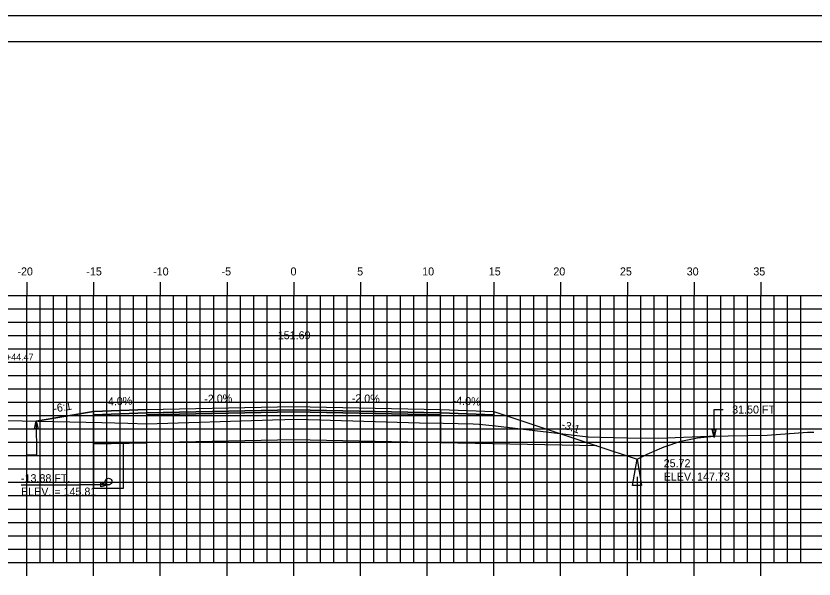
# Model space of a CAD drawing. Extents: x 1147412 to 1147582, y 608981 to 609091.
# Drawn here: x 1147473.9 to 1147533.7, y 609049.1 to 609091.3 of the extents above; entities that cross this region are included whole.
import ezdxf

# ---------------------------------------------------------------- set-up
doc = ezdxf.new("R2010")
doc.units = 0
for name, color, linetype in [('ANNOTATION', 7, 'Continuous'), ('BORDER', 7, 'Continuous'), ('D_Drainage_Ditch_Line', 7, 'Continuous'), ('D_Drainage_Underdrain', 7, 'Continuous'), ('D_Drainage_Underdrain_06in', 7, 'Continuous'), ('D_Roadway_Centerline', 7, 'Continuous'), ('D_Roadway_Centerline_Text', 7, 'Continuous'), ('D_Roadway_Edge_Shoulder', 7, 'Continuous'), ('D_Roadway_Edge_TW', 7, 'Continuous'), ('D_Roadway_Pavement', 7, 'Continuous'), ('D_Roadway_SlopeLines', 7, 'Continuous'), ('D_Roadway_SubGrade', 7, 'Continuous'), ('D_Text_Monospaced', 7, 'Continuous'), ('D_Text_Standard', 7, 'Continuous'), ('H_V ANNOTATION', 7, 'Continuous'), ('MAJOR', 7, 'Continuous'), ('MINOR', 7, 'Continuous'), ('PLOT BOUNDARY', 7, 'Continuous'), ('S_Roadway_Centerline', 7, 'Continuous')]:
    doc.layers.add(name, color=color, linetype=linetype)

msp = doc.modelspace()

# ---------------------------------------------------------------- linework, layer by layer
msp.add_lwpolyline([(1147475.408, 609060.927), (1147479.696, 609061.642), (1147479.697, 609061.642), (1147483.697, 609061.802), (1147494.697, 609062.022), (1147505.697, 609061.802), (1147509.697, 609061.642), (1147517.421, 609059.067), (1147520.421, 609058.067), (1147521.194, 609058.454), (1147522.444, 609059.006), (1147523.694, 609059.415), (1147524.944, 609059.679), (1147526.194, 609059.799)])
at = {"layer": 'BORDER'}
msp.add_lwpolyline([(1147419.698, 608984.335), (1147579.698, 608984.335), (1147579.698, 609089.335), (1147419.698, 609089.335)], close=True, dxfattribs=at)
at = {"layer": 'D_Drainage_Ditch_Line'}
msp.add_line((1147520.421, 609056.755), (1147520.421, 609050.511), dxfattribs=at)
msp.add_lwpolyline([(1147520.749, 609056.099), (1147520.093, 609056.099), (1147520.421, 609058.067)], close=True, dxfattribs=at)
at = {"layer": 'D_Drainage_Underdrain'}
msp.add_lwpolyline([(1147479.697, 609059.222), (1147479.697, 609055.892), (1147481.947, 609055.892), (1147481.947, 609059.267)], close=True, dxfattribs=at)
at = {"layer": 'D_Drainage_Underdrain_06in'}
msp.add_lwpolyline([(1147480.822, 609056.642), (1147480.9, 609056.629), (1147480.969, 609056.594), (1147481.025, 609056.539), (1147481.06, 609056.469), (1147481.072, 609056.392), (1147481.06, 609056.314), (1147481.025, 609056.245), (1147480.969, 609056.189), (1147480.9, 609056.154), (1147480.822, 609056.142), (1147480.745, 609056.154), (1147480.675, 609056.189), (1147480.62, 609056.245), (1147480.585, 609056.314), (1147480.572, 609056.392), (1147480.585, 609056.469), (1147480.62, 609056.539), (1147480.675, 609056.594), (1147480.745, 609056.629)], close=True, dxfattribs=at)
at = {"layer": 'D_Roadway_Edge_Shoulder'}
for points in [[(1147483.697, 609061.802), (1147479.697, 609061.642), (1147479.697, 609061.392), (1147483.697, 609061.552)], [(1147505.697, 609061.802), (1147509.697, 609061.642), (1147509.697, 609061.392), (1147505.697, 609061.552)]]:
    msp.add_lwpolyline(points, close=True, dxfattribs=at)
at = {"layer": 'D_Roadway_Edge_TW'}
msp.add_lwpolyline([(1147483.697, 609061.552), (1147483.697, 609061.802), (1147494.697, 609062.022), (1147505.697, 609061.802), (1147505.697, 609061.552), (1147494.697, 609061.772)], close=True, dxfattribs=at)
at = {"layer": 'D_Roadway_Pavement'}
msp.add_lwpolyline([(1147483.697, 609061.385), (1147483.697, 609061.552), (1147494.697, 609061.772), (1147505.697, 609061.552), (1147505.697, 609061.385), (1147494.697, 609061.605)], close=True, dxfattribs=at)
at = {"layer": 'D_Roadway_SlopeLines'}
for points in [[(1147479.697, 609061.642), (1147475.408, 609060.927)], [(1147520.421, 609058.067), (1147521.194, 609058.454), (1147522.444, 609059.006), (1147523.694, 609059.415), (1147524.944, 609059.679), (1147526.194, 609059.799)], [(1147517.421, 609059.067), (1147520.421, 609058.067)]]:
    msp.add_lwpolyline(points, dxfattribs=at)
at = {"layer": 'D_Roadway_SubGrade'}
for points in [[(1147483.697, 609061.385), (1147483.697, 609061.552), (1147479.697, 609061.392), (1147479.697, 609061.642), (1147479.696, 609061.642), (1147479.697, 609059.222), (1147483.697, 609059.302)], [(1147483.697, 609059.302), (1147483.697, 609061.385), (1147494.697, 609061.605), (1147505.697, 609061.385), (1147505.697, 609059.302), (1147494.697, 609059.522)], [(1147505.697, 609061.385), (1147505.697, 609061.552), (1147509.697, 609061.392), (1147509.697, 609061.642), (1147509.698, 609061.642), (1147517.421, 609059.067), (1147505.697, 609059.302)]]:
    msp.add_lwpolyline(points, close=True, dxfattribs=at)
at = {"layer": 'D_Text_Standard'}
msp.add_line((1147474.26, 609056.142), (1147478.675, 609056.142), dxfattribs=at)
for points in [[(1147526.194, 609059.704), (1147526.192, 609061.789), (1147526.872, 609061.789)], [(1147475.408, 609060.927), (1147475.413, 609058.361), (1147474.733, 609058.361)], [(1147480.822, 609056.142), (1147479.355, 609056.142), (1147478.675, 609056.142)]]:
    msp.add_lwpolyline(points, dxfattribs=at)
for points in [[(1147475.408, 609060.927), (1147475.554, 609060.345), (1147475.263, 609060.344)], [(1147526.194, 609059.704), (1147526.048, 609060.286), (1147526.339, 609060.286)], [(1147480.822, 609056.142), (1147480.24, 609055.996), (1147480.24, 609056.287)]]:
    msp.add_lwpolyline(points, close=True, dxfattribs=at)
at = {"layer": 'MAJOR'}
for p, q in [((1147474.697, 609071.337), (1147474.697, 609070.335)), ((1147479.697, 609071.337), (1147479.697, 609070.335)), ((1147484.697, 609071.337), (1147484.697, 609070.335)), ((1147489.697, 609071.337), (1147489.697, 609070.335)), ((1147494.697, 609071.337), (1147494.697, 609070.335)), ((1147499.697, 609071.337), (1147499.697, 609070.335)), ((1147504.697, 609071.337), (1147504.697, 609070.335)), ((1147509.697, 609071.337), (1147509.697, 609070.335)), ((1147514.697, 609071.337), (1147514.697, 609070.335)), ((1147519.697, 609071.337), (1147519.697, 609070.335)), ((1147524.697, 609071.337), (1147524.697, 609070.335)), ((1147529.697, 609071.337), (1147529.697, 609070.335)), ((1147424.697, 609070.335), (1147564.697, 609070.335)), ((1147424.697, 609070.335), (1147564.697, 609070.335)), ((1147474.697, 609050.335), (1147474.697, 609070.335)), ((1147479.697, 609050.335), (1147479.697, 609070.335)), ((1147484.697, 609050.335), (1147484.697, 609070.335)), ((1147489.697, 609050.335), (1147489.697, 609070.335)), ((1147494.697, 609050.335), (1147494.697, 609070.335)), ((1147499.697, 609050.335), (1147499.697, 609070.335)), ((1147504.697, 609050.335), (1147504.697, 609070.335)), ((1147509.697, 609050.335), (1147509.697, 609070.335)), ((1147514.697, 609050.335), (1147514.697, 609070.335)), ((1147519.697, 609050.335), (1147519.697, 609070.335)), ((1147524.697, 609050.335), (1147524.697, 609070.335)), ((1147529.697, 609050.335), (1147529.697, 609070.335)), ((1147424.697, 609065.335), (1147564.697, 609065.335)), ((1147424.697, 609060.335), (1147564.697, 609060.335)), ((1147424.697, 609055.335), (1147564.697, 609055.335)), ((1147424.697, 609050.335), (1147564.697, 609050.335)), ((1147424.697, 609050.335), (1147564.697, 609050.335)), ((1147474.697, 609049.333), (1147474.697, 609050.335)), ((1147479.697, 609049.333), (1147479.697, 609050.335)), ((1147484.697, 609049.333), (1147484.697, 609050.335)), ((1147489.697, 609049.333), (1147489.697, 609050.335)), ((1147494.697, 609049.333), (1147494.697, 609050.335)), ((1147499.697, 609049.333), (1147499.697, 609050.335)), ((1147504.697, 609049.333), (1147504.697, 609050.335)), ((1147509.697, 609049.333), (1147509.697, 609050.335)), ((1147514.697, 609049.333), (1147514.697, 609050.335)), ((1147519.697, 609049.333), (1147519.697, 609050.335)), ((1147524.697, 609049.333), (1147524.697, 609050.335)), ((1147529.697, 609049.333), (1147529.697, 609050.335))]:
    msp.add_line(p, q, dxfattribs=at)
at = {"layer": 'MINOR'}
for p, q in [((1147475.697, 609050.335), (1147475.697, 609070.335)), ((1147476.697, 609050.335), (1147476.697, 609070.335)), ((1147477.697, 609050.335), (1147477.697, 609070.335)), ((1147478.697, 609050.335), (1147478.697, 609070.335)), ((1147480.697, 609050.335), (1147480.697, 609070.335)), ((1147481.697, 609050.335), (1147481.697, 609070.335)), ((1147482.697, 609050.335), (1147482.697, 609070.335)), ((1147483.697, 609050.335), (1147483.697, 609070.335)), ((1147485.697, 609050.335), (1147485.697, 609070.335)), ((1147486.697, 609050.335), (1147486.697, 609070.335)), ((1147487.697, 609050.335), (1147487.697, 609070.335)), ((1147488.697, 609050.335), (1147488.697, 609070.335)), ((1147490.697, 609050.335), (1147490.697, 609070.335)), ((1147491.697, 609050.335), (1147491.697, 609070.335)), ((1147492.697, 609050.335), (1147492.697, 609070.335)), ((1147493.697, 609050.335), (1147493.697, 609070.335)), ((1147495.697, 609050.335), (1147495.697, 609070.335)), ((1147496.697, 609050.335), (1147496.697, 609070.335)), ((1147497.697, 609050.335), (1147497.697, 609070.335)), ((1147498.697, 609050.335), (1147498.697, 609070.335)), ((1147500.697, 609050.335), (1147500.697, 609070.335)), ((1147501.697, 609050.335), (1147501.697, 609070.335)), ((1147502.697, 609050.335), (1147502.697, 609070.335)), ((1147503.697, 609050.335), (1147503.697, 609070.335)), ((1147505.697, 609050.335), (1147505.697, 609070.335)), ((1147506.697, 609050.335), (1147506.697, 609070.335)), ((1147507.697, 609050.335), (1147507.697, 609070.335)), ((1147508.697, 609050.335), (1147508.697, 609070.335)), ((1147510.697, 609050.335), (1147510.697, 609070.335)), ((1147511.697, 609050.335), (1147511.697, 609070.335)), ((1147512.697, 609050.335), (1147512.697, 609070.335)), ((1147513.697, 609050.335), (1147513.697, 609070.335)), ((1147515.697, 609050.335), (1147515.697, 609070.335)), ((1147516.697, 609050.335), (1147516.697, 609070.335)), ((1147517.697, 609050.335), (1147517.697, 609070.335)), ((1147518.697, 609050.335), (1147518.697, 609070.335)), ((1147520.697, 609050.335), (1147520.697, 609070.335)), ((1147521.697, 609050.335), (1147521.697, 609070.335)), ((1147522.697, 609050.335), (1147522.697, 609070.335)), ((1147523.697, 609050.335), (1147523.697, 609070.335)), ((1147525.697, 609050.335), (1147525.697, 609070.335)), ((1147526.697, 609050.335), (1147526.697, 609070.335)), ((1147527.697, 609050.335), (1147527.697, 609070.335)), ((1147528.697, 609050.335), (1147528.697, 609070.335)), ((1147530.697, 609050.335), (1147530.697, 609070.335)), ((1147531.697, 609050.335), (1147531.697, 609070.335)), ((1147532.697, 609050.335), (1147532.697, 609070.335)), ((1147424.697, 609069.335), (1147564.697, 609069.335)), ((1147424.697, 609068.335), (1147564.697, 609068.335)), ((1147424.697, 609067.335), (1147564.697, 609067.335)), ((1147424.697, 609066.335), (1147564.697, 609066.335)), ((1147424.697, 609064.335), (1147564.697, 609064.335)), ((1147424.697, 609063.335), (1147564.697, 609063.335)), ((1147424.697, 609062.335), (1147564.697, 609062.335)), ((1147424.697, 609061.335), (1147564.697, 609061.335)), ((1147424.697, 609059.335), (1147564.697, 609059.335)), ((1147424.697, 609058.335), (1147564.697, 609058.335)), ((1147424.697, 609057.335), (1147564.697, 609057.335)), ((1147424.697, 609056.335), (1147564.697, 609056.335)), ((1147424.697, 609054.335), (1147564.697, 609054.335)), ((1147424.697, 609053.335), (1147564.697, 609053.335)), ((1147424.697, 609052.335), (1147564.697, 609052.335)), ((1147424.697, 609051.335), (1147564.697, 609051.335))]:
    msp.add_line(p, q, dxfattribs=at)
at = {"layer": 'PLOT BOUNDARY'}
msp.add_lwpolyline([(1147411.604, 608981.276), (1147581.604, 608981.276), (1147581.604, 609091.276), (1147411.604, 609091.276)], close=True, dxfattribs=at)
at = {"layer": 'S_Roadway_Centerline'}
msp.add_lwpolyline([(1147473.137, 609060.973), (1147480.324, 609060.826), (1147482.271, 609060.76), (1147483.69, 609060.711), (1147493.107, 609061.017), (1147494.957, 609061.055), (1147504.126, 609060.801), (1147505.884, 609060.777), (1147508.154, 609060.713), (1147508.6, 609060.698), (1147509.815, 609060.577), (1147516.763, 609059.745), (1147519.664, 609059.659), (1147522.04, 609059.635), (1147525.81, 609059.792), (1147530.174, 609059.875), (1147533.194, 609060.09), (1147533.676, 609060.092)], dxfattribs=at)

# ---------------------------------------------------------------- texts
at = {"layer": 'ANNOTATION'}
for s, rotation, p in [('-4.0%', 2.29061, (1147480.513, 609062.075)), ('-2.0%', 1.14576, (1147488, 609062.288)), ('-2.0%', 358.85424, (1147499.04, 609062.335)), ('-4.0%', 357.70939, (1147506.593, 609062.167)), ('-6:1', 9.46427, (1147476.731, 609061.561)), ('-3:1', 341.56521, (1147514.709, 609060.425))]:
    msp.add_text(s, height=0.6, rotation=rotation, dxfattribs=at).set_placement(p)
at = {"layer": 'D_Roadway_Centerline'}
for s, p in [('C', (1147494.692, 609062.022)), ('L', (1147494.697, 609062.014))]:
    msp.add_text(s, height=0.0146, dxfattribs=at).set_placement(p)
at = {"layer": 'D_Roadway_Centerline_Text'}
msp.add_text('151.69', height=0.6, dxfattribs=at).set_placement((1147493.499, 609067.054))
at = {"layer": 'D_Text_Monospaced'}
msp.add_text('STA. 366+44.47', height=0.49998, dxfattribs=at).set_placement((1147470.347, 609065.47))
at = {"layer": 'D_Text_Standard'}
for s, p in [('31.50 FT', (1147527.552, 609061.489)), ('25.72', (1147522.421, 609057.467)), ('-13.88 FT.', (1147474.26, 609056.342)), ('ELEV. 147.73', (1147522.421, 609056.465)), ('ELEV. = 145.81', (1147474.26, 609055.342))]:
    msp.add_text(s, height=0.6, dxfattribs=at).set_placement(p)
at = {"layer": 'H_V ANNOTATION'}
for s, p in [('-20', (1147473.991, 609071.835)), ('-15', (1147479.154, 609071.835)), ('-10', (1147484.162, 609071.835)), ('-5', (1147489.288, 609071.835)), ('0', (1147494.457, 609071.835)), ('5', (1147499.449, 609071.835)), ('10', (1147504.323, 609071.835)), ('15', (1147509.315, 609071.835)), ('20', (1147514.151, 609071.835)), ('25', (1147519.143, 609071.835)), ('30', (1147524.146, 609071.835)), ('35', (1147529.138, 609071.835))]:
    msp.add_text(s, height=0.6, dxfattribs=at).set_placement(p)
at = {"layer": 'S_Roadway_Centerline'}
for s, p in [('C', (1147494.952, 609061.055)), ('L', (1147494.957, 609061.048))]:
    msp.add_text(s, height=0.0146, dxfattribs=at).set_placement(p)

doc.saveas('drawing.dxf')
